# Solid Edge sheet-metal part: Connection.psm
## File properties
Title: Connection
Author: windows
Template: Iso Metric Sheet Metal.psm
Last saved by: windows
Revision: 5
Application: Solid Edge
Density: 2712,000 kg/m^3
Accuracy: 0,990
Material Thickness: 1,00 mm
Bend Radius: 1,00 mm
Relief Width: 1,00 mm
Relief Length: 0,00 mm
Neutral Factor: 0,330
Minimum Arc Length: 0,10 mm
Deviational Tolerance: 0,10 mm
Username: windows
Material: Aluminum, 3004
Face Style: Aluminum
Fill Style: ANSI38(Aluminum)
Virtual Style: ANSI38(Aluminum)
Grouping: Metals\Aluminium Alloys
LibraryName: Materials
Coef. of Thermal Exp: 2.3e-05
Thermal Conductivity: 170.0
Specific Heat: 920.0
Modulus of Elasticity: 68947570000.0
Poisson's Ratio: 0.33
Yield Stress: 68947570.0
Ultimate Stress: 179263682.0
Elongation: 0.0
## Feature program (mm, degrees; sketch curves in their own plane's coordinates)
base tab "unnamed BaseTab 1"
dimple "Dimple_1"
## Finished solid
Body 1: solid body, 12 faces, 18 edges, 8 vertices.
  Faces by surface: plane 8, cylinder 2, torus 2
  Edges by curve: line 12, circle 6
Bounding box of the edges (mm; curved faces can reach further): 10.000 x 10.000 x 11.000, from (-5, -5, -10) to (5, 5, 1).
Cylindrical faces by radius (mm): R1.5 x1, R2.5 x1
Toroidal faces (ring radius, tube radius in mm): R1.5 r1 x1, R2.5 r1 x1
Planar faces by outward normal: +x 1, +y 1, +z 2, -x 1, -y 1, -z 2
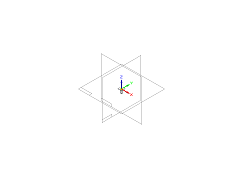
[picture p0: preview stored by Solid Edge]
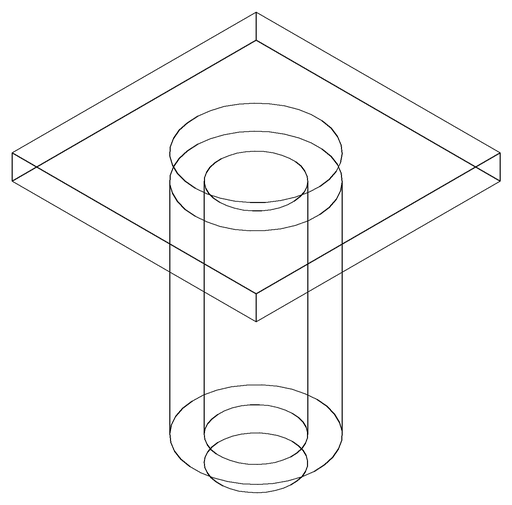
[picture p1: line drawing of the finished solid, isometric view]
